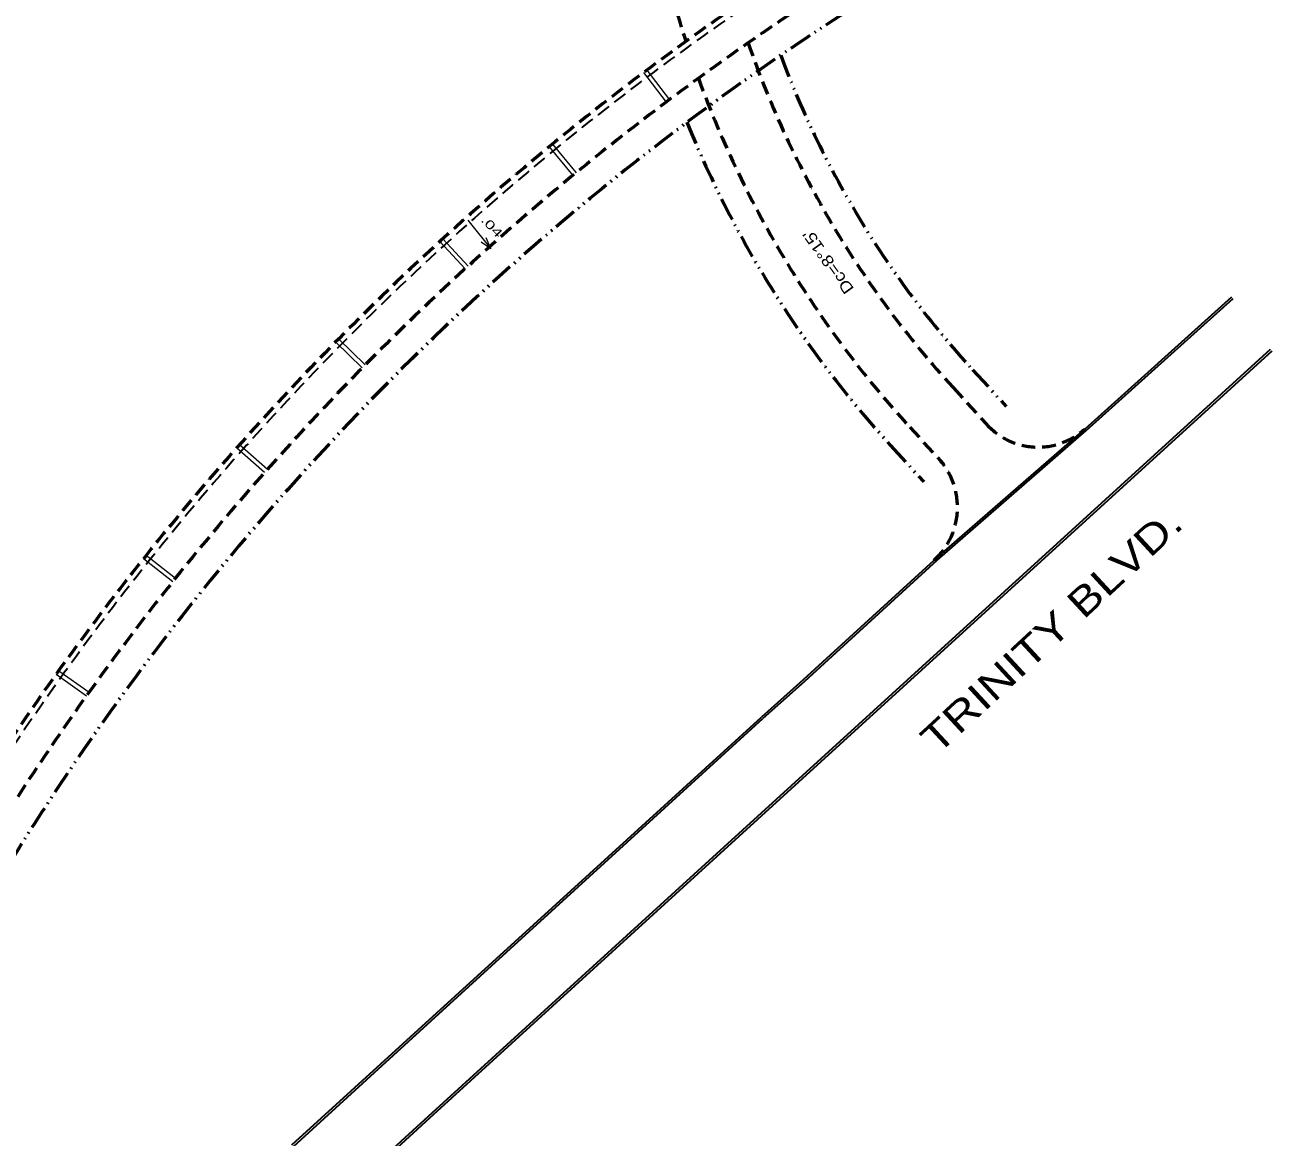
# Model space of a CAD drawing. Extents: x 2354993 to 2372084, y 6966390 to 6990057.
# Drawn here: x 2365274 to 2366146, y 6976742 to 6977519 of the extents above; entities that cross this region are included whole.
import ezdxf

# ---------------------------------------------------------------- set-up
doc = ezdxf.new("R2010")
doc.units = 0
doc.header["$LTSCALE"] = 3.2
doc.linetypes.add('DASH_DOUBLE_DOT', pattern=[9.2, 5, -1.2, 0.3, -1.2, 0.3, -1.2])
doc.linetypes.add('MEDIUM_DASHED', pattern=[4.5, 3, -1.5])
for name, color, linetype, lineweight in [('12', 7, 'Continuous', 13), ('15', 7, 'Continuous', 13), ('19', 7, 'Continuous', 13), ('5', 7, 'Continuous', 35), ('60', 7, 'DASH_DOUBLE_DOT', 53)]:
    doc.layers.add(name, color=color, linetype=linetype, lineweight=lineweight)

msp = doc.modelspace()

# ---------------------------------------------------------------- linework, layer by layer
at = {"layer": '12'}
for p, q in [((2365706.401, 6977485.815), (2365722.116, 6977465.102)), ((2365708.801, 6977487.615), (2365724.516, 6977466.902)), ((2365640.437, 6977433.972), (2365657.038, 6977413.96)), ((2365642.756, 6977435.874), (2365659.357, 6977415.864)), ((2365564.022, 6977367.745), (2365581.648, 6977348.63)), ((2365566.238, 6977369.767), (2365583.863, 6977350.651)), ((2365493.27, 6977299.715), (2365511.87, 6977281.548)), ((2365491.163, 6977297.58), (2365509.764, 6977279.414)), ((2365422.062, 6977223.666), (2365441.588, 6977206.498)), ((2365424.054, 6977225.908), (2365443.58, 6977208.74)), ((2365356.917, 6977146.204), (2365377.315, 6977130.082)), ((2365358.787, 6977148.548), (2365379.185, 6977132.425)), ((2365295.908, 6977065.407), (2365317.122, 6977050.374)), ((2365297.654, 6977067.845), (2365318.867, 6977052.811))]:
    msp.add_line(p, q, dxfattribs=at)
at = {"layer": '19'}
msp.add_line((2365599.587, 6977362.553), (2365592.852, 6977367.425), dxfattribs=at)
msp.add_lwpolyline([(2365583.635, 6977382.811), (2365599.587, 6977362.553), (2365596.433, 6977370.238)], dxfattribs=at)
at = {"layer": '5'}
for p, q in [((2366014.751, 6977236.761), (2366117.49, 6977329.187)), ((2366015.754, 6977235.646), (2366118.493, 6977328.072)), ((2365556.136, 6976756.497), (2366144.675, 6977292.612)), ((2365557.146, 6976755.388), (2366145.685, 6977291.503)), ((2365909.577, 6977145.178), (2366014.751, 6977236.761)), ((2365911.696, 6977145.082), (2366015.754, 6977235.646)), ((2365815.567, 6977059.288), (2365909.577, 6977145.178)), ((2365816.579, 6977058.181), (2365911.696, 6977145.082)), ((2365815.58, 6977059.3), (2365788.866, 6977035.463)), ((2365816.579, 6977058.181), (2365789.865, 6977034.344)), ((2365523.82, 6976791.997), (2365789.865, 6977034.344)), ((2365461.706, 6976735.455), (2365523.82, 6976791.997)), ((2365407.189, 6976620.909), (2365556.136, 6976756.497)), ((2365408.199, 6976619.8), (2365557.146, 6976755.388))]:
    msp.add_line(p, q, dxfattribs=at)
at = {"layer": '5', "linetype": 'MEDIUM_DASHED', "lineweight": 53}
for p, q in [((2365922.738, 6977265.696), (2365946.284, 6977239.915)), ((2365892.463, 6977238.046), (2365916.009, 6977212.265))]:
    msp.add_line(p, q, dxfattribs=at)
at = {"layer": '5'}
msp.add_lwpolyline([(2365460.696, 6976736.564), (2365522.81, 6976793.106), (2365788.855, 6977035.453)], dxfattribs=at)
at = {"layer": '5', "linetype": 'MEDIUM_DASHED', "lineweight": 53}
for centre, radius, start, end in [((2366864.416, 6975944.503), 1927.859, 114.19653, 168.16581), ((2366864.416, 6975944.503), 1901.859, 114.19652, 168.16581), ((2366434.455, 6977733.014), 733.994, 186.19583, 197.93267), ((2366434.455, 6977733.014), 692.994, 199.07293, 222.40345), ((2366434.455, 6977733.014), 733.994, 200.00964, 222.40345), ((2365982.096, 6977272.621), 48.5, 222.40417, 312.31108), ((2365875.852, 6977182.092), 50, 312.41557, 42.40327)]:
    msp.add_arc(centre, radius, start, end, dxfattribs=at)
at = {"layer": '5', "linetype": 'MEDIUM_DASHED'}
msp.add_arc((2366864.416, 6975944.503), 1923.859, 114.19652, 168.16581, dxfattribs=at)
at = {"layer": '60'}
for p, q in [((2365936.398, 6977278.172), (2365959.944, 6977252.391)), ((2365878.803, 6977225.57), (2365902.349, 6977199.789))]:
    msp.add_line(p, q, dxfattribs=at)
for centre, radius, start, end in [((2366864.416, 6975944.503), 1881.859, 114.65077, 155.69784), ((2366434.455, 6977733.014), 674.494, 200.396, 222.40345), ((2366434.455, 6977733.014), 752.494, 202.00282, 222.40345)]:
    msp.add_arc(centre, radius, start, end, dxfattribs=at)

# ---------------------------------------------------------------- texts
at = {"layer": '15', "width": 1.25}
msp.add_text('TRINITY BLVD.', height=20, rotation=42.787, dxfattribs=at).set_placement((2365911.739, 6977008.548))
at = {"layer": '19'}
for s, height, rotation, width, p in [('.04', 6, 313.815, 1.55, (2365592.215, 6977382.374)), ("Dc=8°15'", 8, 125.518, 1.2, (2365853.851, 6977334.737))]:
    msp.add_text(s, height=height, rotation=rotation, dxfattribs=dict(at, width=width)).set_placement(p)

doc.saveas('drawing.dxf')
